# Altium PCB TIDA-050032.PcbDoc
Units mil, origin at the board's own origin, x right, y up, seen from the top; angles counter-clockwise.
Board outline 2509.99 x 1210.36 mil, 2 copper layers (Top Layer, Bottom Layer), stack 62 mil thick; 20 components, 13 nets, 51 pads, 7 vias.
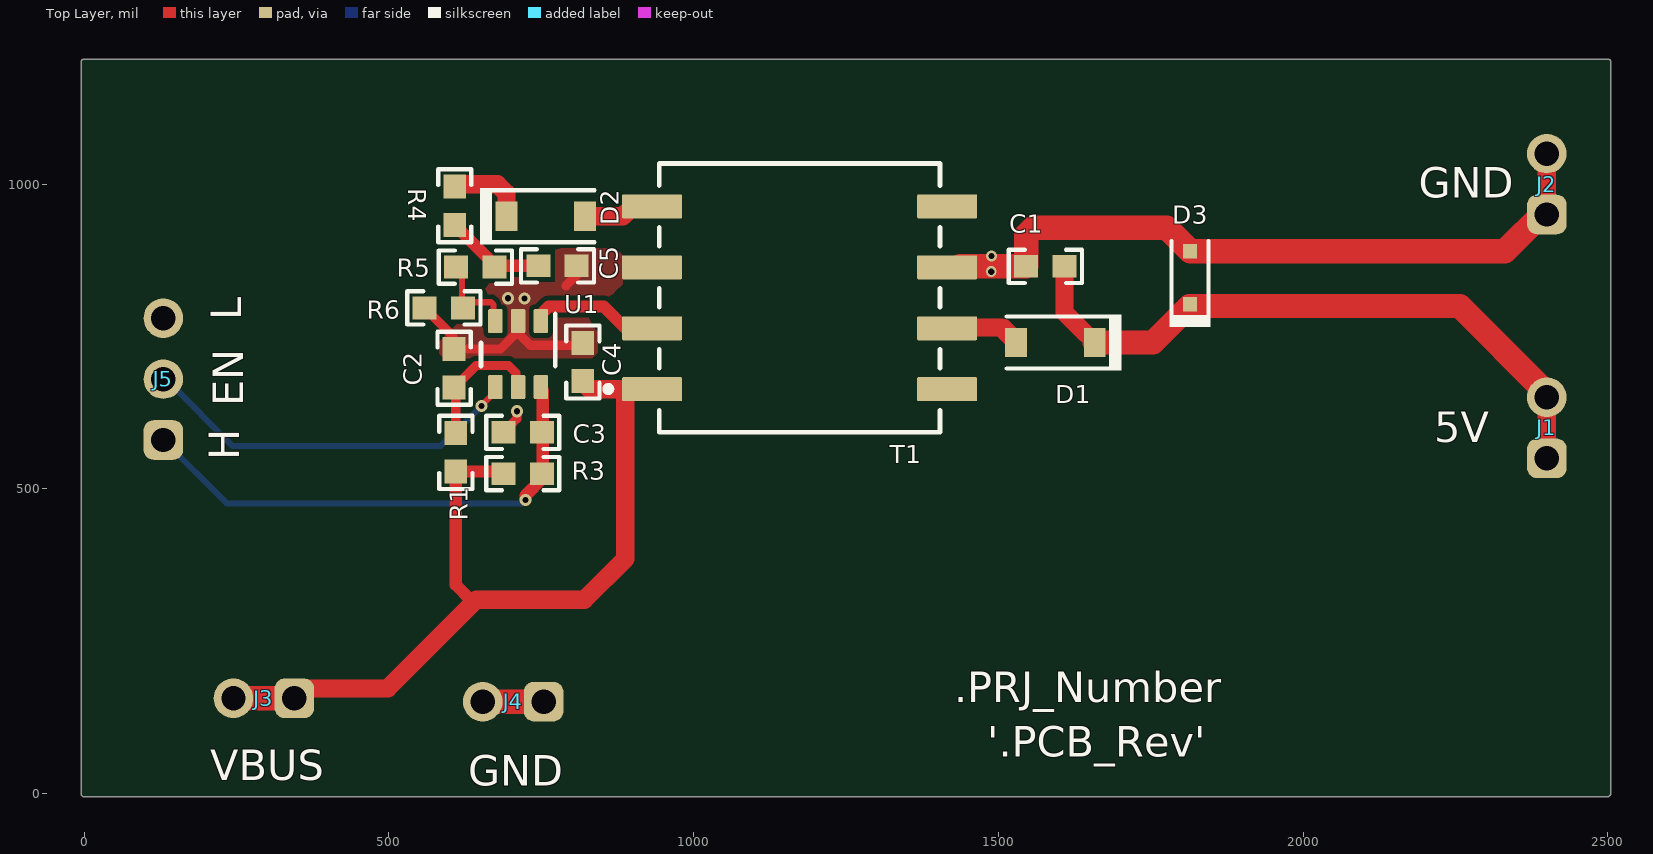
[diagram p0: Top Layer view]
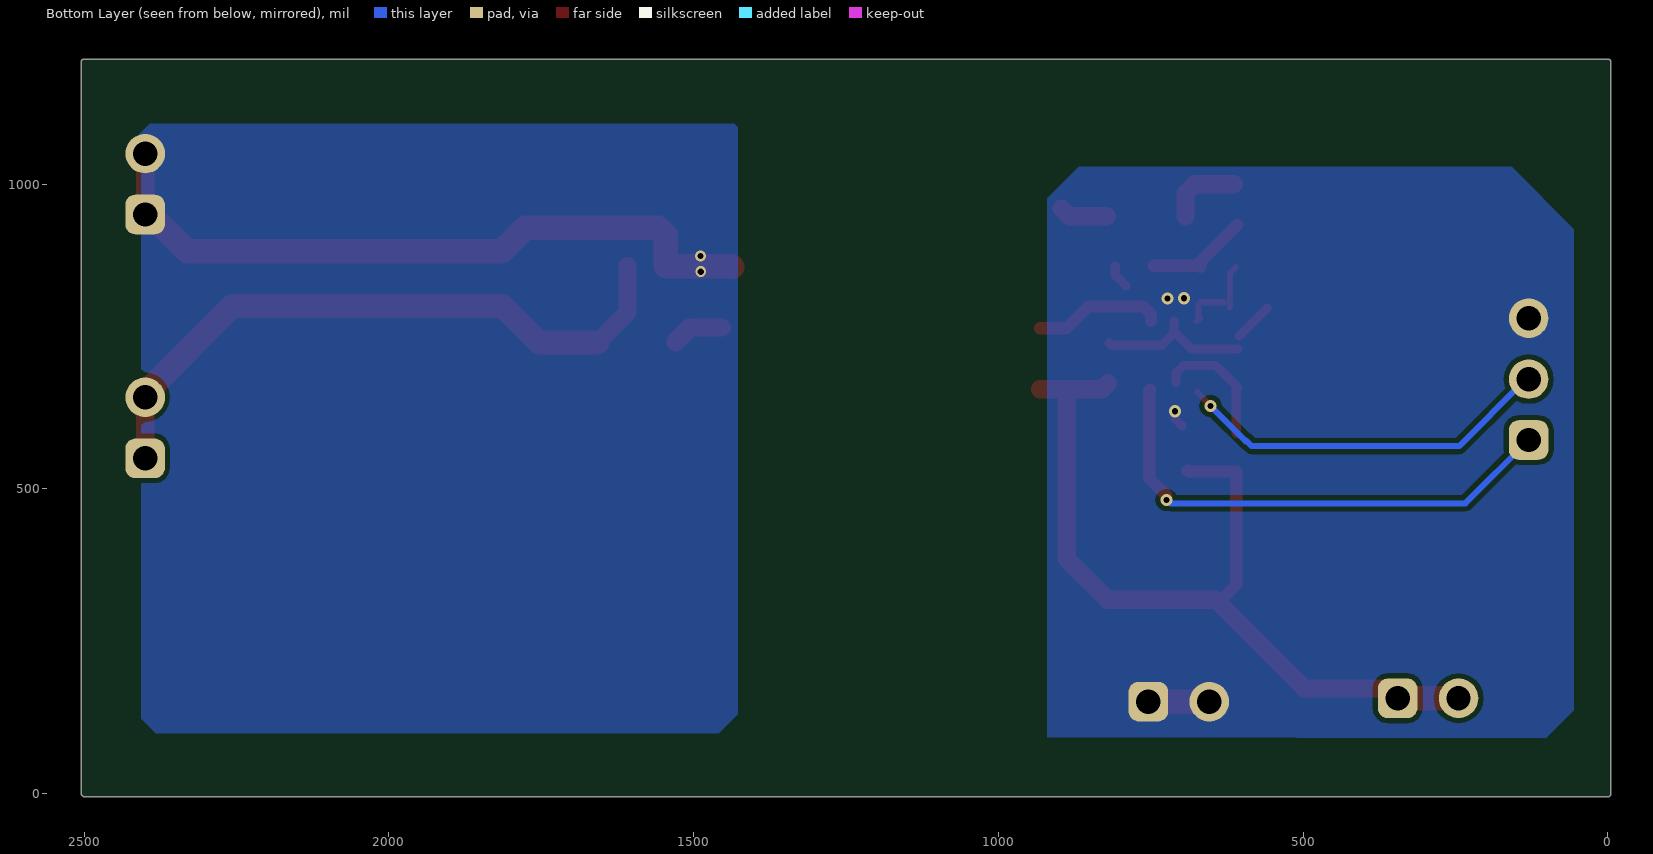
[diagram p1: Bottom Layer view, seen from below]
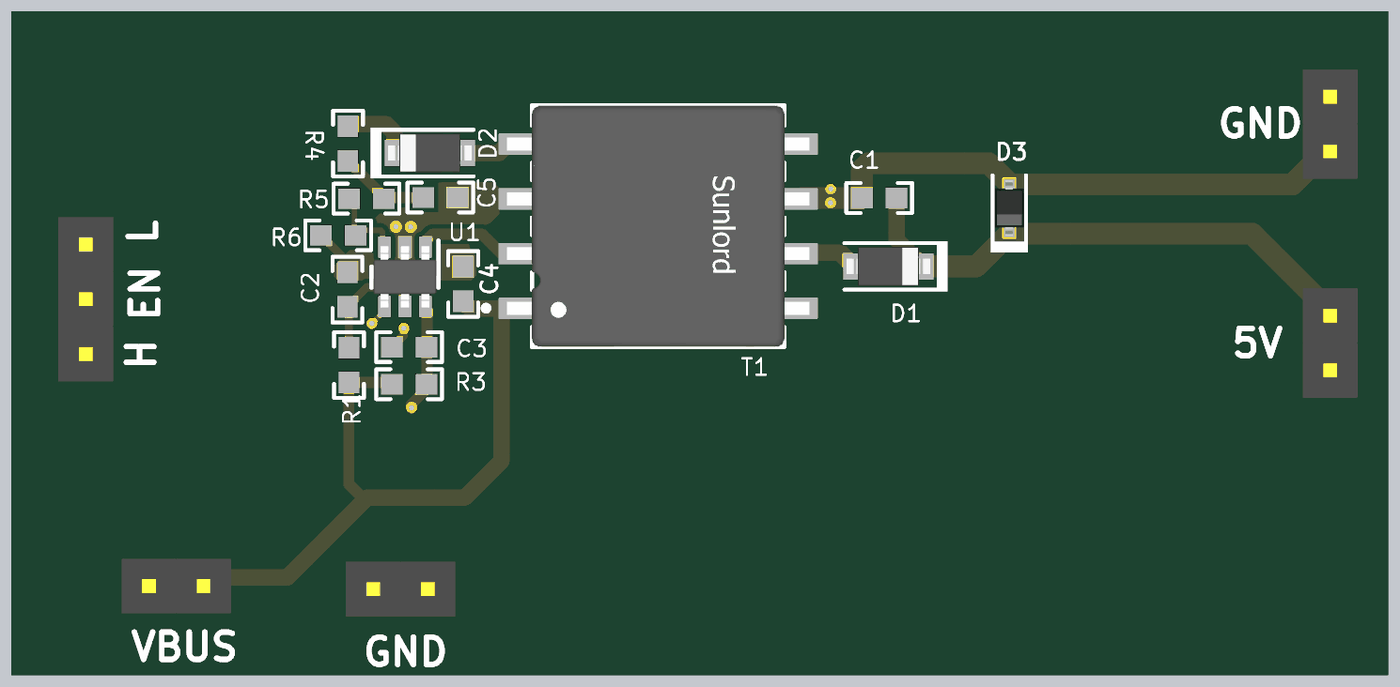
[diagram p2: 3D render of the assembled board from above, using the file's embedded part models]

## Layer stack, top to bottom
Top Solder: solder mask 0.4, Solder Resist, Dk 3.5
Top Layer: signal copper 1.4
Dielectric1: core 59.2, FR-4, Dk 4.8
Bottom Layer: signal copper 1.4
Bottom Solder: solder mask 0.4, Solder Resist, Dk 3.5

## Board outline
-4.87,-0.06 cw(c0.06,0.85) -4.96,0.85 -4.96,1199.94 cw(c0.06,1199.94) 0.06,1204.96 2500.02,1204.96 cw(c2500.02,1199.94) 2505.04,1199.94 2505.04,0.48 cw(c2500.02,0.48) 2503.55,-3.08 2503.57,-3.06 2502.7,-3.93 2502.71,-3.92 cw(c2499.15,-0.39) 2499.15,-5.4 0.13,-5.4 cw(c0.13,-0.39)

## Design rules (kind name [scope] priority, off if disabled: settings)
AcuteAngle [All] p1: minimum=4.50000000000000E+0001 checktracksonly=FALSE
AssemblyTestPointUsage [All] p1: valid=2
Clearance "U1 Clearance" [InComponent('U1')] p1: gap=8 ignorepadtopadclearanceinfootprint=FALSE except(0: Arc-Hole Track-Hole SMDPad-Hole THPad-Hole Via-Hole Fill-Hole Poly-Hole Region-Hole Text-Hole)
Clearance Clearance_BoardEdge [OnCopper and Not InComponentClass('Logo') and not InComponentClass('FiducialMark') and not InRegion(1000,500,4000,800) vs IsKeepOut] p2: gap=30 ignorepadtopadclearanceinfootprint=FALSE except(0: Arc-Hole Track-Hole SMDPad-Hole THPad-Hole Via-Hole Fill-Hole Poly-Hole Region-Hole Text-Hole)
Clearance [All] p3: gap=8 ignorepadtopadclearanceinfootprint=FALSE except(0: Arc-Hole Track-Hole SMDPad-Hole THPad-Hole Via-Hole Fill-Hole Poly-Hole Region-Hole Text-Hole)
ComponentClearance ComponentClearance_MountingHoles_FiducialMarks [InComponentClass('Mounting Holes') vs InComponentClass('FiducialMark')] p1: gap=50 collisioncheckmode=3 verticalgap=10 showdistances=FALSE
ComponentClearance ComponentClearance_SHUNT [InComponentClass('Shunt')] p2: gap=0 collisioncheckmode=3 verticalgap=0 showdistances=FALSE
ComponentClearance ComponentClearance_Logo [All] p3: gap=10 collisioncheckmode=3 verticalgap=10 showdistances=FALSE
ComponentClearance ComponentClearance_ScrewToNut [(HasFootprint('NY PMS 440 0025 PH')) vs (HasFootprint('Keystone_1902C'))] p4: gap=5 collisioncheckmode=3 verticalgap=10 showdistances=FALSE
ComponentClearance ComponentClearance_MountingHoles [InComponentClass('Mounting Holes')] p5: gap=250 collisioncheckmode=3 verticalgap=100000 showdistances=FALSE
ComponentClearance ComponentClearance_SmallPassives [HasFootprint('0201*') or HasFootprint('0402*') or HasFootprint('0508') or HasFootprint('0603*') or HasFootprint('0612') or HasFootprint('0805*') or HasFootprint('0815*') or HasFootprint('0830*') or HasFootprint('1206*') or HasFootprint('1210*') or HasFootprint('1808*') or HasFootprint('1812*') or HasFootprint('1825*') or HasFootprint('2010*') or HasFootprint('2220*') or HasFootprint('2225*') or HasFootprint('2512*') or HasFootprint('2728*') or HasFootprint('3518*') vs HasFootprint('0201*') or HasFootprint('0402*') or HasFootprint('0508') or HasFootprint('0603*') or HasFootprint('0612') or HasFootprint('0805*') or HasFootprint('0815*') or HasFootprint('0830*') or HasFootprint('1206*') or HasFootprint('1210*') or HasFootprint('1808*') or HasFootprint('1812*') or HasFootprint('1825*') or HasFootprint('2010*') or HasFootprint('2220*') or HasFootprint('2225*') or HasFootprint('2512*') or HasFootprint('2728*') or HasFootprint('3518*')] p6: gap=20 collisioncheckmode=3 verticalgap=10 showdistances=FALSE
ComponentClearance ComponentClearance_THtoSMT [IsThruComponent vs IsSMTComponent] p7 off: gap=10 collisioncheckmode=3 verticalgap=100000 showdistances=FALSE
ComponentClearance ComponentClearance_THtoTH [IsThruComponent vs IsThruComponent] p8: gap=10.11 collisioncheckmode=3 verticalgap=100000 showdistances=FALSE
ComponentClearance [All] p9: gap=10 collisioncheckmode=3 verticalgap=10 showdistances=FALSE
DiffPairsRouting [All] p1: maxlimit=100 minlimit=10 mostfreqgap=10 toplayer_minwidth=15 toplayer_maxwidth=15 toplayer_prefwidth=15 bottomlayer_minwidth=15 bottomlayer_maxwidth=15 bottomlayer_prefwidth=15 maxuncoupledlength=1000
FabricationTestPointUsage TestPointUsage [All] p1: valid=2 allowmultiple=FALSE
FabricationTestpoint Testpoint [All] p1: side=3 testpointundercomponent=TRUE minsize=40 maxsize=100 preferedsize=60 minholesize=0 maxholesize=40 preferedholesize=32 testpointgrid=1 allowsidetop=TRUE allowsidebottom=TRUE usegrid=TRUE gridtolerance=0.01
FanoutControl Fanout_LCC [IsLCC] p1: bgadir=Out bgaviamode=Centered fanoutstyle=Auto fanoutdirection=Alternating viagrid=1 // Fanout_LCC (Default Rule)
FanoutControl Fanout_BGA [IsBGA] p2: bgadir=Out bgaviamode=Centered fanoutstyle=Auto fanoutdirection=Alternating viagrid=1 // Fanout_BGA (Default Rule)
FanoutControl Fanout_Default [All] p4: bgadir=Out bgaviamode=Centered fanoutstyle=Auto fanoutdirection=Alternating viagrid=1 // Fanout_Default (Default Rule)
FanoutControl Fanout_Small [(CompPinCount < 5)] p5: bgadir=Out bgaviamode=Centered fanoutstyle=Auto fanoutdirection=OutThenIn viagrid=1 // Fanout_Small (Default Rule)
HoleSize [All] p1: absolutevalues=TRUE maxlimit=100 minlimit=8 maxpercent=80.000 minpercent=20.000
HoleToHoleClearance [All] p1: gap=1 allowstackedmicrovias=TRUE
MinimumAnnularRing MinimumAnnularRing_small [TouchesRoom('BGA_Room')] p1: minimumring=2.8
MinimumAnnularRing MinimumAnnularRing_ThermalPadVias [IsVia and InAnyComponent] p2: minimumring=5.91
MinimumAnnularRing [All] p3: minimumring=4
MinimumSolderMaskSliver MinimumSolderMaskSliver_Logo [InComponentClass('Logo') vs InComponentClass('Logo')] p1: minsoldermaskwidth=0.7
MinimumSolderMaskSliver [All] p2: minsoldermaskwidth=3
PlaneClearance [All] p1: clearance=10
PlaneConnect [All] p1: planeconnectstyle=Direct reliefexpansion=10 reliefentries=4 reliefconductorwidth=10 reliefairgap=10
PolygonConnect PolygonConnect-TH-Relief [IsPoly vs (IsThruPin)  And Not (InComponent('U3'))  And Not (InComponent('U4'))] p1: connectstyle=Direct reliefconductorwidth=20 reliefentries=4 polygonreliefangle="90 Angle" airgapwidth=10
PolygonConnect PolygonConnect-DirectConn [All] p2: connectstyle=Direct reliefconductorwidth=10 reliefentries=4 polygonreliefangle="90 Angle" airgapwidth=10
PolygonConnect [All] p3: connectstyle=Relief reliefconductorwidth=10 reliefentries=4 polygonreliefangle="90 Angle" airgapwidth=10
RoutingVias ThermalPadVias [IsVia and InAnyComponent] p1: holewidth=7.87 width=19.68 viastyle="Through Hole" minholewidth=7.87 minwidth=19.68 maxholewidth=12.99 maxwidth=23.62
RoutingVias [All] p2: holewidth=10 width=22 viastyle="Through Hole" minholewidth=4 minwidth=10 maxholewidth=100 maxwidth=100
SMDToCorner [All] p1: distance=0
SilkToBoardRegionClearance [Not ((IsComment or IsDesignator) And (Hide <> 'False')) and not InRegion(1000,500,4000,800)] p1:
SilkToSilkClearance SilkToSilkClearance_Pb-FreeLogo [(HasFootprint('Pb-Free_Overlay_Medium') OR HasFootprint('Pb-Free_Overlay_Small')) vs (HasFootprint('Pb-Free_Overlay_Medium') OR HasFootprint('Pb-Free_Overlay_Small'))] p1: silktosilkclearance=0
SilkToSilkClearance [All] p2: silktosilkclearance=3
SilkToSolderMaskClearance SilkToComonentPadClearance [IsPad and InAnycomponent] p1 off: minsilkscreentomaskgap=5 clearancetoexposedcopper=TRUE
SilkToSolderMaskClearance "Silk to Solder Mask Opening" [All] p2 off: minsilkscreentomaskgap=4 clearancetoexposedcopper=TRUE
SolderMaskExpansion [All] p1: expansion=1
Width [All] p1: maxlimit=100 minlimit=6 preferedwidth=10 checkconnectedcopper=TRUE
13 further rules are at their usual default settings.

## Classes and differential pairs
component class Header: J1 J2 J3 J4 J5

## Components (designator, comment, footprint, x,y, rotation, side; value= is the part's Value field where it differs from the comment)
C1 "GRM188R61A226ME15D" 0603 1577.21,865.05 r180 top value=22uF
C2 "Capacitor" 0603 607.07,697.69 r90 top value=0.1uF
C3 "Capacitor" 0603 719.59,592.62 r180 top value=0.1uF
C4 "Capacitor" 0603 818.21,708 r90 top value=2.2uF
C5 "GRM188R61A224KA01D" 0603 776.66,865.81 r0 top value=0.22uF
D1 "DIODE_SCHOTTKY" SOD-123 1593.72,740 r180 top value=40V
D2 "DIODE" SOD-123 757.35,947.17 r0 top value=100V
D3 "MMSZ5232BS-7-F" SOD-323 1814.45,846.37 r90 top value=5.6V
J1 "Header_2x1" TSW-102-07-G-S 2400,600 r90 top
J2 "Header_2x1" TSW-102-07-G-S 2400,1000 r90 top
J3 "Header_2x1" TSW-102-07-G-S 294.97,156.23 r180 top
J4 "Header_2x1" TSW-102-07-G-S 703.84,150.75 r180 top
J5 "Header_3x1" TSW-103-07-G-S 130,680 r90 top
R1 "Resistor" 0603 609.83,559.7 r270 top value=10.0k
R3 "RMCF0603ZT0R00" 0603 719.59,524.78 r0 top value=0
R4 "RC0603FR-0719R6L" 0603 608.05,964.41 r270 top value=19.6
R5 "RC0603FR-071K62L" 0603 641.88,863.76 r0 top value=1.62k
R6 "CRCW0603332RFKEA" 0603 590.18,796.71 r180 top value=332
T1 "RTSB070403B100K2T" FP-RTSB070403B100K2T_SMD8-MFG 1173.92,813.34 r270 top
U1 "TLV61046ADBVR" DBV0006A_N 712.03,721.01 r270 top

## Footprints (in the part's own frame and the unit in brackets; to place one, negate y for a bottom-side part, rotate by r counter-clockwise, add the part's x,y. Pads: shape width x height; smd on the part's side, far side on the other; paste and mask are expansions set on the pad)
0603 [mm] "0603 from SM-752 data"
  rect 1x0.95 smd: 1(-0.8,0) 2(0.8,0)
  silkscreen extent -1.52,-0.69 1.52,0.69, body extent -0.87,-0.47 0.87,0.47, height 1
DBV0006A_N [mm] "SOT23, 6-Leads, Body 2.9x1.6mm, Pitch 0.95mm, Lead Span 2.8mm, IPC Medium Density"
  rrect17% 1x0.6 smd: 1(-1.375,0.95) 2(-1.375,0) 3(-1.375,-0.95) 4(1.375,-0.95) 5(1.375,0) 6(1.375,0.95)
  silkscreen extent -1.68,-1.55 0.5,1.55, body extent -1.42,-1.46 1.42,1.46, height 1.12
FP-RTSB070403B100K2T_SMD8-MFG [mm]
  rrect10% 1x2.5 smd paste+0 mask+0: 1(3.81,-6.15) 2(1.27,-6.15) 3(-1.27,-6.15) 4(-3.81,-6.15) 5(-3.81,6.15) 6(-1.27,6.15) 7(1.27,6.15) 8(3.81,6.15)
  silkscreen extent -5.6,-8.1 5.6,5.85, body extent -5.7,-7.5 5.7,7.5, height 0.25
SOD-123 [mm] "On Semi recommended land pattern"
  rect 0.915x1.22 smd: 1(-1.637,0) 2(1.637,0)
  silkscreen extent -2.74,-1.17 2.03,1.17, body extent -1.93,-0.9 1.93,0.9, height 1.35
SOD-323 [mm] "NXP recommended land pattern"
  rect 0.6x0.6 smd paste-0.05: 1(-1.1,0) 2(1.1,0)
  silkscreen extent -2.06,-0.86 1.53,0.86, body extent -1.3,-0.67 1.3,0.68, height 1.1
TSW-102-07-G-S [mm] "Samtec 100mil, 1x2, 230 mil above insulator"
  rrect50% 1.65x1.65 hole 1.016: 1(-1.27,0)
  round 1.65 hole 1.016: 2(1.27,0)
  body extent -2.54,-1.27 2.54,1.27, height 8.38
TSW-103-07-G-S [mm] "Samtec 100mil, 1x3, 230 mil above insulator"
  rrect50% 1.65x1.65 hole 1.016: 1(-2.54,0)
  round 1.65 hole 1.016: 2(0,0) 3(2.54,0)
  body extent -3.81,-1.27 3.81,1.27, height 8.38

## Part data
C1: library part CMP-0007324-5, "CAP, CERM, 22 uF, 10 V, +/- 20%, X5R, 0603", Cap_Case=0603, Manufacturer=MuRata, Supplier Part Number 1=490-10476-1-ND, TempCo=X5R, Tolerance_%=20%, Value1=Unknown, Value2=10V, ValueDisplayed=22uF
C2 C3: library part CMP-0007334-5, "CAP, CERM, 0.1 uF, 16 V, +/- 10%, X5R, 0603", Cap_Case=0603, Manufacturer=MuRata, PartNumber=GRM188R61C104KA01D, Supplier Part Number 1=GRM188R61C104KA01D-ND, TempCo=X5R, Tolerance_%=10%, Value1=Unknown, Value2=16V, ValueDisplayed=0.1uF
C4: library part CMP-0007356-5, "CAP, CERM, 2.2 uF, 35 V, +/- 10%, X5R, 0603", Cap_Case=0603, Manufacturer=MuRata, PartNumber=GRM188R6YA225KA12D, Supplier Part Number 1=490-7204-6-ND, TempCo=X5R, Tolerance_%=10%, Value1=Unknown, Value2=35V, ValueDisplayed=2.2uF
C5: library part CMP-0007322-5, "CAP, CERM, 0.22 uF, 10 V, +/- 10%, X5R, 0603", Cap_Case=0603, Manufacturer=MuRata, Supplier Part Number 1=490-1537-1-ND, TempCo=X5R, Tolerance_%=10%, Value1=Unknown, Value2=10V, ValueDisplayed=0.22uF
D1: library part CMP-0028526-2, "Diode, Schottky, 40 V, 0.5 A, SOD-123", Manufacturer="ON Semiconductor", PartNumber=MBR0540T1G, Value1=0.5A, Value2=0.51V
D2: library part CMP-0076974-2, "Diode, Switching, 100 V, 0.15 A, SOD-123", Manufacturer="Micro Commercial Components", PartNumber=1N4148W-TP, Value1=0.15A, Value2=1.25V
D3: library part CMP-0005855-3, "Diode, Zener, 5.6 V, 200 mW, SOD-323", Manufacturer="Diodes Inc.", Power_W=200mW, Value1=0.2W
J1 J2 J3 J4: library part CMP-0075405-2, "Header, 100mil, 2x1, Gold, TH", Color=Black, Current_A=6.3A, Manufacturer=Samtec, PartNumber=TSW-102-07-G-S, Supplier Part Number 1=SAM1029-02-ND, Voltage_V=550V
J5: library part CMP-0075407-2, "Header, 100mil, 3x1, Gold, TH", Color=Black, Current_A=6.3A, Manufacturer=Samtec, PartNumber=TSW-103-07-G-S, Supplier Part Number 1=SAM1029-03-ND, Voltage_V=550V
R1: library part CMP-0022746-5, "RES, 10.0 k, 1%, 0.1 W, 0603", Manufacturer=Yageo, PartNumber=RC0603FR-0710KL, Power_W=100mW, Supplier Part Number 1=311-10.0KHRCT-ND, TempCo="100 ppm/C", Tolerance_%=1%, Value2=0.1W, Value_Code=10k0, ValueDisplayed=10.0k
R3: library part CMP-0023343-3, "RES, 0, 1%, 0.1 W, AEC-Q200 Grade 0, 0603", Manufacturer="Stackpole Electronics Inc", Power_W=100mW, Supplier Part Number 1=RMCF0603ZT0R00CT-ND, TempCo=ppm/C, Tolerance_%=1%, Value2=0.1W, Value_Code=0
R4: library part CMP-0022863-4, "RES, 19.6, 1%, 0.1 W, 0603", Manufacturer=Yageo, Power_W=100mW, Supplier Part Number 1=311-19.6HRCT-ND, TempCo="100 ppm/C", Tolerance_%=1%, Value2=0.1W, Value_Code=19R6, ValueDisplayed=19.6
R5: library part CMP-0022884-5, "RES, 1.62 k, 1%, 0.1 W, 0603", Manufacturer=Yageo, Power_W=100mW, Supplier Part Number 1=311-1.62KHRCT-ND, TempCo="100 ppm/C", Tolerance_%=1%, Value2=0.1W, Value_Code=1k62, ValueDisplayed=1.62k
R6: library part CMP-0022337-5, "RES, 332, 1%, 0.1 W, AEC-Q200 Grade 0, 0603", Manufacturer=Vishay-Dale, Power_W=100mW, Supplier Part Number 1=541-332HCT-ND, TempCo="100 ppm/C", Tolerance_%=1%, Value2=0.1W, Value_Code=332R, ValueDisplayed=332
T1: library part CMP-0087597-1, "TRANSFORMER SMD", Manufacturer=Sunlord
U1: library part CMP-0013231-2, "28-V Output Voltage Boost Converter with Power Diode and Isolation Switch, DBV0006A (SOT-6)", Alternate Manufacturer="Texas Instruments", Alternate PartNumber=TLV61046ADBVT

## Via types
v1: diameter 20, hole 10, Top Layer to Bottom Layer, 5 vias
v2: diameter 18, hole 10, Top Layer to Bottom Layer, 2 vias

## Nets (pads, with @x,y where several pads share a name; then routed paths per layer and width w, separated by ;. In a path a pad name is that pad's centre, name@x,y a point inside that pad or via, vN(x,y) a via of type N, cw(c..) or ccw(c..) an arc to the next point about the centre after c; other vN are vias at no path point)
5V: C1.1 D1.1 D3.1 J1.1 J1.2 | length 1228.1
  Top Layer w30: C1.1 1608.7,789.11 D1.1@1643.88,753.92 ; 2276.02,777.95 2400,653.98 J1.2 J1.1
  Top Layer w40: D1.1 1753.78,740 1813.61,799.83 2256.88,799.83 J1.2@2398.05,658.65
EN: J5.2 U1.4 | length 616.1
  Top Layer w10: v1(651.72,635.88) 673.21,657.36 U1.4@673.21,659.14
  Bottom Layer w10: J5.2@139.44,674.47 244,569.9 584.29,569.9 593.62,579.24 ; 592.14,576.42 v1@650.53,634.8
FB: R5.1 R6.1 U1.3 | length 145
  Top Layer w10: R5.1 619.84,854.31 R6.1@619.84,797.57 ; R6.1@629.75,805.79 629.99,806.03 667.7,806.03 671.33,802.4 U1.3@671.33,778.44 ; U1.3@669.16,780.62 U1.3@671.33,778.44 ; U1.3 U1.3@671.33,778.44
GND: C2.2 C3.2 C4.2 C5.2 J4.1 J4.2 J5.3 R6.2 T1.3 U1.2 | length 487.7
  Top Layer w15: R6.2 604.75,750.65 ; C2.2 682.74,729.19 U1.2@712.03,758.48 ; C3.2@698.81,603.41 710.07,614.67 v1(710.07,627.22) ; U1.2 U1.2@712.03,758.48 ; U1.2@712.72,759.16 U1.2@712.03,758.48 ; 790.37,832.98 808.16,850.77 C5.2 ; C4.2 814.15,735.45 732.04,735.45 712.03,755.45 U1.2@712.03,758.48
  Top Layer w40: J4.2 J4.1
  other v1: 722.62,812.24 695.59,812.57
NetC2_1: C2.1 R1.1 U1.5 | length 211.8
  Top Layer w15: C2.1 642.93,702.06 696.55,702.06 708.47,690.14 U1.5@708.47,674.56 ; C2.1@607.76,665.35 609.83,663.28 R1.1
NetD1_2: D1.2 T1.7 | length 114
  Top Layer w30: T1.7@1453.95,764.58 1454.05,764.68 1504.57,764.68 D1.2 ; 1508.75,763.34 D1.2@1528.83,743.25
NetD2_1: D2.1 R4.1 | length 122.6
  Top Layer w30: R4.1@613.91,999.53 678.07,999.53 692.88,984.72 D2.1
NetD2_2: D2.2 T1.4 | length 79.9
  Top Layer w30: D2.2 883.72,947.17 T1.4@896.45,959.9
NetT1_2: T1.2 U1.1 | length 211.6
  Top Layer w20: U1.1 749.44,786.32 761.92,798.81 ; 763.77,798.92 852.53,798.92 888.12,763.34 T1.2
SGND: C1.2 D3.2 J2.1 J2.2 T1.6 | length 1248.1
  Top Layer w30: 2330.65,889.79 2400,959.14 J2.2
  Top Layer w40: T1.6@1436.6,863.94 1437.7,865.05 C1.2 1545.71,916.42 1557.7,928.41 1776.54,928.41 1815.16,889.79 2330.65,889.79 2331.04,889.79 J2.1@2396.08,954.83
  other v2: 1488.36,856.13 1488.75,881.72
VBUS: C4.1 J3.1 J3.2 R1.2 R3.1 T1.1 | length 1408.1
  Top Layer w10: 290,142.14 290,156.23
  Top Layer w20: 634.08,318.1 609.83,342.35 R1.2 688.58,528.2 R3.1@690.08,529.69 ; 649.04,318.09 649.78,317.35
  Top Layer w30: J3.1@360.87,172.29 498.05,172.29 643.85,318.09 649.04,318.09 821.12,318.09 887.87,384.84 T1.1@887.87,656.31 ; C4.1@820.46,672.98 830.1,663.34 T1.1
  Top Layer w40: J3.2 290,156.23 J3.1@335.06,156.23
VIN: C3.1 J5.1 R3.2 U1.6 | length 824.4
  Top Layer w20: v1(724.1,481.69) 724.1,488.97 752.37,517.24 752.37,661.14 U1.6@751.09,662.43
  Bottom Layer w10: J5.1 233.98,476.02 v1@718.34,476.02
VSEN: C5.1 R4.2 R5.2 | length 167
  Top Layer w20: R4.2 667.89,873.07 R5.2@667.89,868.04 ; R5.2@668.67,863.7 670.79,865.81 C5.1
pads on no net: T1.5 T1.8

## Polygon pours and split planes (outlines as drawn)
GND on Top Layer "GND_L01_P045" (solid, remove dead copper, pour order 45): 582.96,741.6 668.74,827.37 773.14,827.37 842.65,757.86 842.65,723.43 833.64,714.42 589.72,714.42 582.96,721.18
GND on Top Layer "GND_L01_P047" (solid, remove dead copper, pour order 47): 722.99,894.33 872.48,894.33 883.89,882.92 883.89,835.83 870.14,822.08 870.14,809.5 794.95,734.32 690.23,734.32 651.32,773.22 651.32,822.66
GND on Bottom Layer "Bottom Layer-No Net 1" (solid, remove dead copper, pour order 31): 919.95,92.31 919.95,976.65 868.36,1028.24 157.74,1028.24 55.65,926.15 55.65,136.46 101.69,90.42
SGND on Bottom Layer "Bottom Layer-No Net" (solid, remove dead copper, pour order 28): 1427.25,1099.89 1427.25,130.09 1458.81,98.53 2382.2,98.53 2406.07,122.39 2406.07,1069.5 2414.17,1077.61 2392.67,1099.11 2165.91,1099.11

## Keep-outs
Keep-Out Layer:
  text ".Layer_Name" at 577,-858.49 h60

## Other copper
Top Layer:
  text ".Layer_Name" at 577,-858.49 h60
Bottom Layer:
  text ".Layer_Name" at 577,-858.49 h60

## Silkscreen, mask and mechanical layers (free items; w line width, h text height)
Top Overlay:
  text "GND" at 2189.76,977.51 h50
  text "L" at 257.53,776.38 h50 r90
  text "EN" at 261.36,635.25 h50 r90
  text "5V" at 2215.3,576.25 h50
  text "H" at 254.46,546.5 h50 r90
  text ".PRJ_Number" at 1428.06,149.35 h50
  text "'.PCB_Rev'" at 1482.19,60.56 h50
  text "VBUS" at 207.18,21.79 h50
  text "GND" at 630.27,12.55 h50
  text ".Layer_Name" at 577,-858.49 h60
Bottom Overlay:
  text ".Layer_Name" at 577,-858.49 h60
Top Paste:
  text ".Layer_Name" at 577,-858.49 h60
Bottom Paste:
  text ".Layer_Name" at 577,-858.49 h60
Top Solder:
  text ".Layer_Name" at 577,-858.49 h60
  text ".Layer_Name" at 577,-858.49 h60
Bottom Solder:
  text ".Layer_Name" at 577,-858.49 h60
Drill Guide:
  text ".Layer_Name" at 577,-858.49 h60
M1 Board Outline:
  lines w10: 0.06,0.85 0.06,1199.94 2500.02,1199.94 2500.02,0.48 2499.15,-0.39 0.13,-0.39
  text ".Layer_Name" at 577,-858.49 h60
M2 Board Dimensions:
  rectangle: 0,-275 125,-150
  rectangle: 125,-400 500,-275
  lines w7: 0,-275 1000,-275 ; 125,-400 125,-150 ; 250,-400 250,-150 ; 500,-400 500,-150 ; 750,-400 750,-150 ; 0,-400 1000,-400 1000,-150 0,-150 0,-400
  text ".Layer_Name" at 577,-858.49 h60
M3 3D STEP Top:
  text ".Layer_Name" at 577,-858.49 h60
M4 3D STEP Bottom:
  text ".Layer_Name" at 577,-858.49 h60
M5 Assembly Top:
  lines w10: -292,-930.17 6308,-930.17 ; -292,-726.83 6310,-726.83 ; -292,-523.5 -292,-1133.5 3713,-1133.5 6310,-1133.5 6310,-523.5 -291.5,-523.5 -291.5,-1133.5 1284,-1133.5 ; 2173,-1133.5 2173,-523.5 ; 3440,-726.83 3440,-523.5 ; 4280,-726.83 4280,-523.5 ; 4902,-1140 4902,-937.17
  text "COMPONENTS MARKED 'DNP' SHOULD NOT BE POPULATED." at 1153.5,-318.5 h60
  text "ASSEMBLY VARIANT:" at 1153,-434 h60
  text ".VariantName" at 2189,-434 h60
  text "PCB VIEWED FROM TOP SIDE" at -228.5,-655.67 h60
  text "BOARD #:" at 2248,-655.67 h60
  text ".PRJ_Number" at 2793.5,-655.67 h60
  text "REV:" at 3638,-655.67 h60
  text ".PCB_Rev" at 3929.5,-655.67 h60
  text "SVN REV:" at 4476,-655.67 h60
  text ".VersionControl_RevNumber" at 4982,-655.67 h60
  text "TID #:" at 2248,-859 h60
  text ".TID" at 2793.5,-859 h60
  text "PLOT NAME =" at -228.5,-1064.34 h60
  text ".plot_File_Name" at 577,-1064.34 h60
  text "GENERATED    :" at 2250,-1064.34 h60
  text ".Print_Date" at 3119.5,-1064.34 h60
  text ".Print_Time" at 3848.5,-1064.34 h60
  text "TEXAS INSTRUMENTS" at 5113,-1064.34 h60
M6 Assembly Bottom:
  lines w10: -292.5,-727.33 6309.5,-727.33 ; -290.5,-930.67 6309.5,-930.67 ; 1115.5,-1140.5 1115.5,-937.67 ; 1737.5,-727.33 1737.5,-524 ; 2577.5,-727.33 2577.5,-524 ; 3844.5,-1134 3844.5,-524 ; 4733.5,-1134 6309,-1134 6309,-524 -292.5,-524 -292.5,-1134 2304.5,-1134 6309.5,-1134 6309.5,-524
  text "COMPONENTS MARKED 'DNP' SHOULD NOT BE POPULATED." at 6102,-318 h60
  text ".VariantName" at 5058,-434 h60
  text "ASSEMBLY VARIANT:" at 6097,-434 h60
  text ".VersionControl_RevNumber" at 1035.5,-656.17 h60
  text "SVN REV:" at 1541.5,-656.17 h60
  text ".PCB_Rev" at 2088,-656.17 h60
  text "REV:" at 2379.5,-656.17 h60
  text ".PRJ_Number" at 3224,-656.17 h60
  text "BOARD #:" at 3769.5,-656.17 h60
  text "PCB VIEWED FROM BOTTOM SIDE" at 6246,-656.17 h60
  text ".TID" at 3224,-859.5 h60
  text "TID #:" at 3769.5,-859.5 h60
  text "TEXAS INSTRUMENTS" at 904.5,-1064.84 h60
  text ".Print_Time" at 2169,-1064.84 h60
  text ".Print_Date" at 2898,-1064.84 h60
  text "GENERATED    :" at 3767.5,-1064.84 h60
  text ".plot_File_Name" at 5440.5,-1064.84 h60
  text "PLOT NAME =" at 6246,-1064.84 h60
M9 Title Sheet:
  drawing of 57 lines, arcs and shapes, not listed
  text "1" at 739.84,8036.5 h70
  text "2" at 3235.5,8036.5 h70
  text "3" at 5724.84,8036.5 h70
  text "4" at 8231.51,8036.5 h70
  text "5" at 10730.5,8036.5 h70
  text "6" at 13235.5,8036.5 h70
  text "A" at -416.5,6893.5 h70
  text "A" at 14383.5,6893.5 h70
  text "B" at -416.5,4513.5 h70
  text "B" at 14383.5,4513.5 h70
  text "C" at -416.5,2138.5 h70
  text "C" at 14383.5,2138.5 h70
  text "PROJECT TITLE:" at 11343.5,277.5 h45
  text ".PRJ_Title" at 11393.5,144.17 h70
  text "DESIGNED FOR:" at 11343.5,-23.5 h45
  text ".PRJ_Customer" at 11393.5,-163.5 h70
  text "D" at -416.5,-231.5 h70
  text "D" at 14383.5,-231.5 h70
  text "FILE NAME:" at 11343.5,-323.5 h45
  text ".PCB_File_Name_No_Path" at 11393.5,-443.5 h70
  text "Texas Instruments (TI) and/or its licensors do not warrant the accuracy or completeness of this specification" at 6374,-605.34 h45
  text "ENGINEER:" at 11343.5,-613.5 h45
  text "LAYOUT BY:" at 12848.5,-613.5 h45
  text "or any information contained therein. TI and/or its licensors do not warrant that this design will meet" at 6329.01,-718 h45
  text ".PRJ_Engineer" at 11393.5,-768.49 h70
  text ".PCB_Layout" at 12899,-768.49 h70
  text "the specifications, will be suitable for your application or fit for any particular purpose, or will operate in" at 6329.01,-830.67 h45
  text ".Layer_Name" at 577,-858.49 h60
  text "ALTIUM DESIGNER VERSION:" at 12848.5,-923.5 h45
  text "an implementation. TI and/or its licensors do not warrant that the design is production worthy. You should" at 6329.01,-943.33 h45
  text "completely validate and test your design implementation to confirm the system functionality for your application." at 6374,-1056 h45
  text ".print_Scale" at 11393.5,-1056.83 h70
  text ".Application_BuildNumber" at 12899,-1056.83 h70
  text "1" at 739.84,-1263.5 h70
  text "2" at 3235.5,-1263.5 h70
  text "3" at 5724.84,-1263.5 h70
  text "4" at 8231.51,-1263.5 h70
  text "5" at 10730.5,-1263.5 h70
  text "6" at 13235.5,-1263.5 h70
M10 Fab Notes:
  drawing of 173 lines, arcs and shapes, not listed
  text "DESIGN INFORMATION" at 12377.02,6201 h60
  text "MIN. TRACK WIDTH:" at 11732.46,6021 h60
  text "8" at 12828.7,6021 h60
  text "MIL" at 12983.46,6021 h60
  text "MIN. CLEARANCE:" at 11732.46,5889 h60
  text "0.2" at 12768.7,5889 h60
  text "mm" at 12983.46,5889 h60
  text "MIN. VIA PAD SIZE:" at 11732.46,5757 h60
  text "24" at 12798.71,5757 h60
  text "MIL" at 12983.46,5757 h60
  text "0.05mm (2MIL)" at 12427.46,5615.29 h60
  text "MINIMUM ANNULAR RING" at 11403.23,5611 h60
  text "EXTERNAL" at 13135.46,5611 h60
  text "PER" at 11603.23,5493 h60
  text "IPC-D-275 CLASS 2 LEVEL C" at 11823.23,5493 h60
  text "MIL, HOLES" at 13311.46,5380.71 h60
  text "+/-" at 12919,5380 h60
  text "+/-" at 13773,5380 h60
  text "REGISTRATION TOLERANCES:" at 11403.23,5375 h60
  text "METAL" at 12603,5375 h60
  text "5" at 13179.2,5375 h60
  text "3" at 14012.2,5375 h60
  text "MIL" at 14128.46,5375 h60
  text "+/-" at 13773,5262 h60
  text "HOLE SIZE TOLERANCE (UNLESS OTHERWISE SPECIFIED):" at 11403.23,5257 h60
  text "3" at 14012.2,5257 h60
  text "MIL" at 14128.46,5257 h60
  text "MATERIAL:" at 11328.46,5047.54 h60
  text "FR-4 High Tg" at 12314.9,4907.21 h60
  text "FR-408" at 11749.46,4898.64 h60
  text "OTHER" at 13237.46,4898.64 h60
  text "X" at 12160,4895 h60
  text "62 MIL (1.6mm) +/-10%" at 12069.56,4735.92 h60
  text "THICKNESS:" at 11403.23,4731.64 h60
  text "X" at 11941.4,4731.64 h60
  text "OTHER" at 13354.46,4731.64 h60
  text "TOLERANCE:" at 11403.23,4573.64 h60
  text "X" at 12242.53,4573.64 h60
  text "ANSI IPC-6012 TYPE 3 CLASS 2" at 12429.48,4573.64 h60
  text "OTHER +/-" at 12429.46,4417.64 h60
  text "BOW & TWIST:" at 11403.23,4260.64 h60
  text "X" at 12242.53,4260.64 h60
  text "ANSI IPC-6012 TYPE 3 CLASS 2" at 12429.48,4260.64 h60
  text "OTHER +/-" at 12429.46,4102.13 h60
  text "DRILLING:" at 11328.46,3963.64 h60
  text "REFERENCE:" at 11403.23,3846.64 h60
  text "X" at 12051.46,3846.64 h60
  text "AS SHOWN" at 12238.46,3846.64 h60
  text "X" at 12952.46,3846.64 h60
  text "NC_DRILL FILES" at 13089.46,3846.64 h60
  text "PTH COPPER THICKNESS:" at 11403.23,3688.64 h60
  text "X" at 12533.46,3688.64 h60
  text "20-30 um" at 12670.46,3688.64 h60
  text "OTHER" at 13387.46,3688.64 h60
  text "BOARD FINISH:" at 11328.46,3529.64 h60
  text "SILKSCREEN:" at 11483.68,3411.64 h60
  text "X" at 12432.46,3411.64 h60
  text "TOP" at 12558.46,3411.64 h60
  text "X" at 12942.46,3411.64 h60
  text "BOTTOM" at 13069.46,3411.64 h60
  text "SILKSCREEN COLOR:" at 11483.68,3244.64 h60
  text "X" at 12431.42,3244.64 h60
  text "WHITE" at 12558.46,3244.64 h60
  text "OTHER" at 13069.46,3244.64 h60
  text "X" at 12562.42,3085.44 h60
  text "GREEN" at 12689.46,3085.44 h60
  text "OTHER" at 13307.46,3085.44 h60
  text "SOLDER RESIST COLOR:" at 11483.68,3074.64 h60
  text "X" at 12562.42,2915.44 h60
  text "MATTE" at 12689.46,2915.44 h60
  text "SEMI-GLOSS" at 13307,2914.8 h60
  text "IMMERSION GOLD (ENIG)" at 12389.46,2726.92 h60
  text "ENEPIG" at 13727,2723.64 h60
  text "SURFACE FINISH:" at 11328.46,2722.64 h60
  text "X" at 12202.51,2722.64 h60
  text "IMM. TIN/SILVER OR EQUIV" at 11658,2565.64 h60
  text "OTHER" at 13089.46,2565.64 h60
  text "ARRAY/PANEL:" at 11328.46,2386.64 h60
  text "CUT AND TRIM PER M1 BOARD OUTLINE" at 12389.46,2382.35 h60
  text "N.C. ROUTE" at 12389.46,2230.64 h60
  text "X" at 13068.46,2230.64 h60
  text "V. SCORE" at 13255.46,2230.64 h60
  text "CERTIFICATION:" at 11328.46,2093.64 h60
  text "MATERIALS AND WORKMANSHIP FOR ALL PCBS" at 12053.46,2093.64 h60
  text "TO MEET OR EXCEED THE REQUIREMENTS OF:" at 12053.46,1995.64 h60
  text "X" at 11679.96,1859.13 h60
  text "ANSI IPC-A-600F CLASS ->" at 11818.96,1859.13 h60
  text "X" at 13458.02,1859.13 h60
  text "2" at 13576.96,1859.14 h60
  text "1" at 13261.96,1857.64 h60
  text "3" at 13930.96,1857.64 h60
  text "X" at 12494.02,1699.64 h60
  text "RoHS" at 12630.96,1699.64 h60
  text "OTHER" at 13275.36,1699.64 h60
  text "PER ORDER" at 13672.42,1699.64 h60
  text "ALL BOARDS MUST MEET OR EXCEED UL94-V0 REQUIREMENTS." at 11356,1534 h60
  text "PCB MUST BEAR THE UL94V-0 UL REGISTERED MATERIAL ID NUMBER" at 11356,1414 h60
  text "ADDITIONAL REQUIREMENTS:" at 11328.46,1240.64 h60
  text "MICROSECTION:" at 11403.23,1125.64 h60
  text "YES" at 12308.96,1125.64 h60
  text "REQUIRED" at 13170.46,969.49 h60
  text "BARE BOARD ELEC. TEST:" at 11403.23,966.64 h60
  text "NONE" at 12708.96,966.64 h60
  text "X" at 13043.46,966.64 h60
  text "PER ORDER" at 13762.46,966.64 h60
  text ".Layer_Name" at 577,-858.49 h60
M11 Gerber Information:
  lines w10: -292,-930.17 6308,-930.17 ; -292,-726.83 6310,-726.83 ; -292,-523.5 -292,-1133.5 3713,-1133.5 6310,-1133.5 6310,-523.5 -291.5,-523.5 -291.5,-1133.5 1284,-1133.5 ; 2173,-1133.5 2173,-523.5 ; 3440,-726.83 3440,-523.5 ; 4280,-726.83 4280,-523.5 ; 4902,-1140 4902,-937.17
  text "ALL ARTWORK VIEWED FROM TOP SIDE" at -228.5,-655.67 h60
  text "BOARD #:" at 2248,-655.67 h60
  text ".PRJ_Number" at 2793.5,-655.67 h60
  text "REV:" at 3638,-655.67 h60
  text ".PCB_Rev" at 3929.5,-655.67 h60
  text "SVN REV:" at 4476,-655.67 h60
  text ".VersionControl_RevNumber" at 4982,-655.67 h60
  text "LAYER NAME =" at -228.5,-858.49 h60
  text "TID #:" at 2248,-859 h60
  text ".TID" at 2793.5,-859 h60
  text "PLOT NAME =" at -228.5,-1064.34 h60
  text ".plot_File_Name" at 577,-1064.34 h60
  text "GENERATED    :" at 2250,-1064.34 h60
  text ".Print_Date" at 3119.5,-1064.34 h60
  text ".Print_Time" at 3848.5,-1064.34 h60
  text "TEXAS INSTRUMENTS" at 5113,-1064.34 h60
M12 Stackup:
  drawing of 191 lines, arcs and shapes, not listed
  text "Layer" at 9797.84,7830 h60
  text "Name" at 10207.76,7830 h60
  text "Material" at 11137.5,7830 h60
  text "Thickness" at 11997.27,7830 h60
  text "Constant" at 12647.1,7830 h60
  text "Board Layer Stack" at 13216.96,7830 h60
  text "1" at 9797.84,7710 h60
  text "Top Overlay" at 10207.76,7710 h60
  text "2" at 9797.84,7590 h60
  text "Top Solder" at 10207.76,7590 h60
  text "Solder Resist" at 11137.5,7590 h60
  text "0.40mil" at 11997.27,7590 h60
  text "3.5" at 12647.1,7590 h60
  text "3" at 9797.84,7470 h60
  text "Top Layer" at 10207.76,7470 h60
  text "Copper" at 11137.5,7470 h60
  text "1.40mil" at 11997.27,7470 h60
  text "4" at 9797.84,7350 h60
  text "Dielectric1" at 10207.76,7350 h60
  text "FR-4" at 11137.5,7350 h60
  text "59.20mil" at 11997.27,7350 h60
  text "4.8" at 12647.1,7350 h60
  text "5" at 9797.84,7230 h60
  text "Bottom Layer" at 10207.76,7230 h60
  text "Copper" at 11137.5,7230 h60
  text "1.40mil" at 11997.27,7230 h60
  text "6" at 9797.84,7110 h60
  text "Bottom Solder" at 10207.76,7110 h60
  text "Solder Resist" at 11137.5,7110 h60
  text "0.40mil" at 11997.27,7110 h60
  text "3.5" at 12647.1,7110 h60
  text "7" at 9797.84,6990 h60
  text "Bottom Overlay" at 10207.76,6990 h60
  text ".Layer_Name" at 577,-858.49 h60
M13 Component Bodies Top:
  text ".Layer_Name" at 577,-858.49 h60
M14 Component Bodies Bottom:
  text ".Layer_Name" at 577,-858.49 h60
M15 Courtyards Top:
  text ".Layer_Name" at 577,-858.49 h60
M16 Courtyards Bottom:
  text ".Layer_Name" at 577,-858.49 h60
Drill Drawing:
  lines w10: 5656.14,3113.96 5683.8,3127.79 5711.46,3113.96 5697.63,3141.62 5711.46,3169.28 5683.8,3155.45 5656.14,3169.28 5669.97,3141.62 5656.14,3113.96 ; 5656.14,3238.42 5656.14,3252.25 5669.97,3266.08 5656.14,3279.91 5656.14,3293.74 5669.97,3293.74 5683.8,3279.91 5697.63,3293.74 5711.46,3293.74 5711.46,3279.91 5697.63,3266.08 5711.46,3252.25 5711.46,3238.42 5697.63,3238.42 5683.8,3252.25 5669.97,3238.42 5656.14,3238.42
  lines w12: 5606,3076.62 7585.4,3076.62 ; 5606,3325.54 7585.4,3325.54 ; 5944.17,2952.17 5944.17,3450 ; 6276.28,2952.17 6276.28,3450 ; 6913.29,2952.17 6913.29,3450 ; 7172.64,2952.17 7172.64,3450 ; 5606,2952.17 7585.4,2952.17 7585.4,3450 5606,3450 5606,2952.17
  text "Symbol" at 5680.68,3362.88 h72
  text "Quantity" at 5981.51,3362.88 h72
  text "Finished Hole Size" at 6313.62,3362.88 h72
  text "Plated" at 6950.62,3362.88 h72
  text "Hole Type" at 7209.98,3362.88 h72
  text "7" at 5981.51,3238.42 h60
  text "10.00mil (0.254mm)" at 6313.62,3238.42 h60
  text "PTH" at 6950.62,3238.42 h60
  text "Round" at 7209.98,3238.42 h60
  text "11" at 5981.51,3113.96 h60
  text "40.00mil (1.016mm)" at 6313.62,3113.96 h60
  text "PTH" at 6950.62,3113.96 h60
  text "Round" at 7209.98,3113.96 h60
  text "18 Total" at 5981.51,2989.5 h60
  text ".Layer_Name" at 577,-858.49 h60

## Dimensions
0,-400 to 1000,-400 on M2 Board Dimensions
0,0 to 0.06,1199.94 on M2 Board Dimensions
0,0 to 2500.02,0.48 on M2 Board Dimensions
